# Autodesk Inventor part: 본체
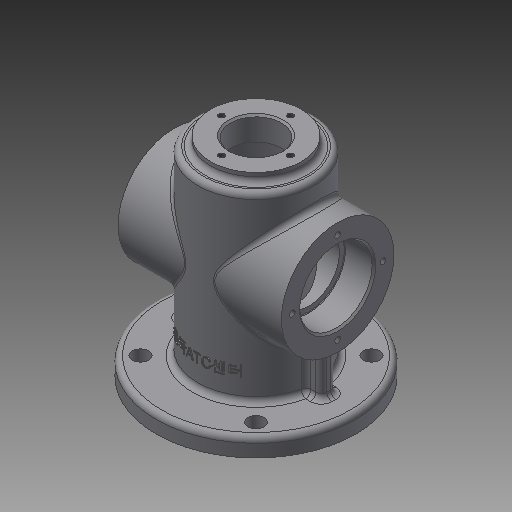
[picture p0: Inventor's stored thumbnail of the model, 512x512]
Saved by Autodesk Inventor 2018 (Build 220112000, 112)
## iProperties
Created: 2020-05
Part Number: 본체
Material: 일반
Document SubType Name: Modeling
Designer: mduedu
Density: 1 g/cm^3
Appearance: 기본값
Author: mduedu
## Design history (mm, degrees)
sketch "스케치1"
  geometry: C1 r 32 at (0, 0); 1 further point
  constraints: 1 centre point, 1 coincident
  dimensions: "d0" = 64 diameter of C1
extrude "돌출1" new body sketch "스케치1" distance "d1" = 110; taper "d2" = 0 deg
feature "쉘1" dims "d3" = 8
fillet "모깎기1" dims "d4" = 3
fillet "모깎기2" dims "d5" = 3
sketch "스케치2"
  geometry: C1 r 25 at (0, 0); 1 further point
  constraints: 1 centre point, 1 coincident
  dimensions: "d6" = 50 diameter of C1
extrude "돌출2" join sketch "스케치2" distance "d7" = 5; taper "d8" = 0 deg
sketch "스케치3"
  geometry: C1 r 14 at (0, 0); 1 further point
  constraints: 1 centre point, 1 coincident
  dimensions: "d9" = 28 diameter of C1
extrude "돌출3" cut sketch "스케치3" extent not by distance; stored distance "d10" = 5; taper "d11" = 0 deg
fillet "모깎기3" dims "d12" = 3
sketch "스케치4"
  geometry: C1 r 32 at (0, 0) reference; C2 r 55 at (0, 0); 1 further point
  constraints: 1 centre point, 1 coincident
  dimensions: "d13" = 110 diameter of C2
extrude "돌출4" join sketch "스케치4" distance "d14" = 10; taper "d15" = 0 deg
sketch "스케치5"
  geometry: L1 (0, 0)-(-31.82, 31.82); L2 (0, 0)-(-45, 0); A1 r 45 centre (0, 0) between (-31.82, 31.82) and (-45, 0); 1 further point
  constraints: 4 end point, 2 point on circle, 1 centre point, 1 coincident, 1 horizontal
  dimensions: "d16" = 90 diameter of A1; "d71" = 45 deg angle of L1 L2
hole "구멍1" sketch "스케치5" at (-31.82, 31.82) diameter "d17" = 9; stored, may be unused: countersink angle "d21" = 90 deg, drill point angle "d23" = 118 deg; dims "d18" = 6, "d19" = 4, "d20" = 2, "d22" = 8
fillet "모깎기4" dims "d27" = 3
node "작업 평면1"
sketch "스케치6"
  geometry: L1 (0, 55)-(0, -55) reference; C1 r 31 at (-65, 0); 2 further points
  constraints: 1 centre point, 1 horizontal alignment, 1 midpoint
  dimensions: "d31" = 62 diameter of C1; "d32" = 65 distance from line of C1.centre L1
extrude "돌출5" join sketch "스케치6" stored distance "d33" = 10; taper "d34" = 0 deg
fillet "모깎기5" dims "d35" = 3
sketch "스케치7"
  geometry: C1 r 31 at (0, 0) reference; C2 r 20 at (0, 0); 1 further point
  constraints: 1 centre point, 1 coincident
  dimensions: "d36" = 40 diameter of C2
extrude "돌출6" cut sketch "스케치7" distance "d37" = 16; taper "d38" = 0 deg
sketch "스케치8"
  geometry: C1 r 20 at (0, 0) reference; C2 r 17 at (0, 0); 1 further point
  constraints: 1 centre point, 1 coincident
  dimensions: "d39" = 34 diameter of C2
extrude "돌출7" cut sketch "스케치8" extent not by distance; stored distance "d40" = 15; taper "d41" = 0 deg
fillet "모깎기6" dims "d42" = 0.3
chamfer "모따기1" distance "d43" = 1; stored, may be unused: second distance "d44" = 2, angle "d45" = 45 deg
chamfer "모따기2" distance "d46" = 1; stored, may be unused: second distance "d47" = 2, angle "d48" = 45 deg
sketch "스케치9" dims "d49" = 50
  geometry: C1 r 31 at (0, 0) reference; 3 further points
  constraints: 2 vertical alignment, 1 coincident, 2 other
hole "구멍2" sketch "스케치9" at (0, 25) diameter "d50" = 3.242; stored, may be unused: countersink angle "d54" = 90 deg, drill point angle "d56" = 118 deg; dims "d51" = 7, "d52" = 4, "d53" = 2, "d55" = 9
sketch "스케치10" dims "d60" = 38
  geometry: 3 further points
  constraints: 2 vertical alignment, 1 coincident, 2 other
hole "구멍3" sketch "스케치10" at (0, 19) diameter "d61" = 3.242; stored, may be unused: countersink angle "d65" = 90 deg, drill point angle "d67" = 118 deg; dims "d62" = 8, "d63" = 4, "d64" = 2, "d66" = 10
sketch "스케치11"
  geometry: L1 (32, 31)-(32, 13) reference; L2 (35, 10)-(52, 10) reference; L3 (55, 7)-(55, 0) reference; L4 (55, 0)-(24, 0) reference; L5 (24, 0)-(24, 48) reference; L6 (24, 48)-(29, 48) reference; L7 (29, 48)-(29, 45.3) reference; L8 (29.3, 45)-(44, 45) reference; L9 (44, 45)-(45, 44) reference; L10 (45, 44)-(45, 41.621) reference; L11 (45, 41.621)-(36, 41.621) reference; L12 (36, 41.621)-(35.026, 40) reference; L13 (35.026, 40)-(36, 38.379) reference; L14 (36, 38.379)-(45, 38.379) reference; L15 (45, 38.379)-(45, 34) reference; L16 (45, 34)-(35, 34) reference; L17 (-32, 13)-(-32, 31) reference; L18 (-35, 34)-(-45, 34) reference; L19 (-45, 34)-(-45, 38.379) reference; L20 (-45, 38.379)-(-36, 38.379) reference; L21 (-36, 38.379)-(-35.026, 40) reference; L22 (-35.026, 40)-(-36, 41.621) reference; L23 (-36, 41.621)-(-45, 41.621) reference; L24 (-45, 41.621)-(-45, 44) reference; L25 (-45, 44)-(-44, 45) reference; L26 (-44, 45)-(-29.3, 45) reference; L27 (-29, 45.3)-(-29, 48) reference; L28 (-29, 48)-(-24, 48) reference; L29 (-24, 48)-(-24, 0) reference; L30 (-24, 0)-(-55, 0) reference; L31 (-55, 0)-(-55, 7) reference; L32 (-52, 10)-(-35, 10) reference; L33 (-25, 113)-(-25, 115) reference; L34 (-25, 115)-(-20.621, 115) reference; L35 (-20.621, 115)-(-20.621, 105) reference; L36 (-20.621, 105)-(-19, 104.026) reference; L37 (-19, 104.026)-(-17.379, 105) reference; L38 (-17.379, 105)-(-17.379, 115) reference; L39 (-17.379, 115)-(-15, 115) reference; L40 (-15, 115)-(-14, 114) reference; L41 (-14, 114)-(-14, 102) reference; L42 (-14, 102)-(-21, 102) reference; L43 (-24, 99)-(-24, 82) reference; L44 (-24, 82)-(-29, 82) reference; L45 (-29, 82)-(-29, 84.7) reference; L46 (-29.3, 85)-(-44, 85) reference; L47 (-44, 85)-(-45, 86) reference; L48 (-45, 86)-(-45, 88.379) reference; L49 (-45, 88.379)-(-36, 88.379) reference; L50 (-36, 88.379)-(-35.026, 90) reference; L51 (-35.026, 90)-(-36, 91.621) reference; L52 (-36, 91.621)-(-45, 91.621) reference; L53 (-45, 91.621)-(-45, 96) reference; L54 (-45, 96)-(-35, 96) reference; L55 (-32, 99)-(-32, 107) reference; L56 (-29, 110)-(-28, 110) reference; L57 (28, 110)-(29, 110) reference; L58 (32, 107)-(32, 99) reference; L59 (35, 96)-(45, 96) reference; L60 (45, 96)-(45, 91.621) reference; L61 (45, 91.621)-(36, 91.621) reference; L62 (36, 91.621)-(35.026, 90) reference; L63 (35.026, 90)-(36, 88.379) reference; L64 (36, 88.379)-(45, 88.379) reference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; A1 r 3 centre (35, 13) between (32, 13) and (35, 10) reference; A2 r 3 centre (52, 7) between (55, 7) and (52, 10) reference; A3 r 0.3 centre (29.3, 45.3) between (29, 45.3) and (29.3, 45) reference; A4 r 0.3 centre (-29.3, 45.3) between (-29.3, 45) and (-29, 45.3) reference; A5 r 3 centre (-52, 7) between (-52, 10) and (-55, 7) reference; A6 r 3 centre (-35, 13) between (-35, 10) and (-32, 13) reference; A7 r 3 centre (-28, 113) between (-28, 110) and (-25, 113) reference; A8 r 3 centre (-21, 99) between (-21, 102) and (-24, 99) reference; A9 r 0.3 centre (-29.3, 84.7) between (-29, 84.7) and (-29.3, 85) reference; A10 r 3 centre (-29, 107) between (-29, 110) and (-32, 107) reference; A11 r 3 centre (28, 113) between (25, 113) and (28, 110) reference; A12 r 3 centre (29, 107) between (32, 107) and (29, 110) reference; A13 r 0.3 centre (29.3, 84.7) between (29.3, 85) and (29, 84.7) reference; A14 r 3 centre (21, 99) between (24, 99) and (21, 102) reference; 1 further point
  constraints: 2 end point, 1 midpoint, 1 perpendicular, 1 point on line, 4 other
  dimensions: "d73" = 5 distance between parallel lines of L81 L19
feature "리브1" sketch "스케치11" dims "d74" = 1, "d75" = 8, "d76" = 0, "d77" = 0, "d78" = 1, "d79" = 1
fillet "모깎기7" dims "d80" = 3
fillet "모깎기8" dims "d81" = 3
node "작업 평면2"
sketch "스케치12"
  geometry: 2 further points
  constraints: 1 vertical alignment, 1 other
  dimensions: "d83" = 25 distance of point (0, 25) point (0, 0)
feature "엠보싱1" sketch "스케치12" dims "d0" = 64, "d84" = 0.5, "d85" = 0
node "솔리드1"
pattern_circular "원형 패턴1" dims angle "d25" = 360 deg
mirror "대칭1"
mirror "대칭2"
pattern_circular "원형 패턴2" dims angle "d58" = 360 deg
mirror "대칭3"
pattern_circular "원형 패턴3" dims angle "d69" = 360 deg
mirror "대칭4"
node "투영된 루프1"
node "투영된 루프2"
node "절단 모서리 투영1"
other parameters: "d30" = -45
